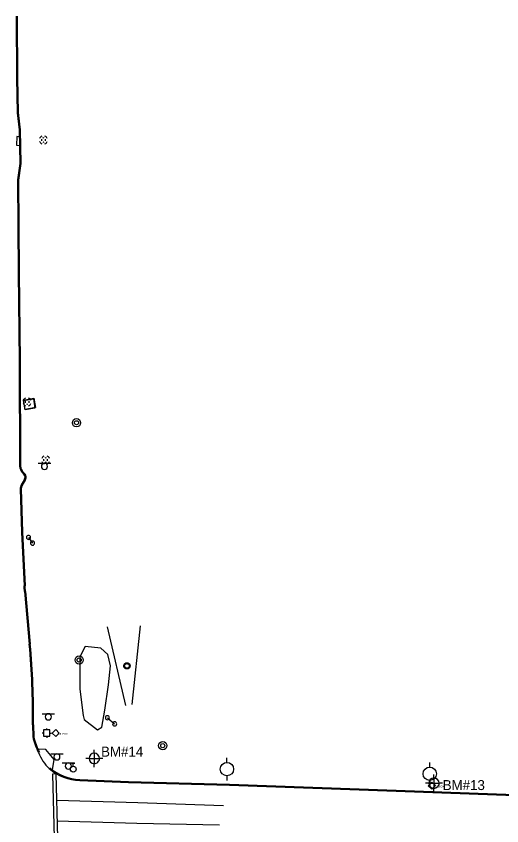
# Model space of a CAD drawing. Extents: x 2145380 to 2157287, y 139568 to 149130.
# Drawn here: x 2145661.6 to 2145954.5, y 143157.2 to 143645.3 of the extents above; entities that cross this region are included whole.
import ezdxf

# ---------------------------------------------------------------- set-up
doc = ezdxf.new("R2010")
doc.units = 0
for name, color, linetype in [('Default', 7, 'Continuous'), ('SURV_Benchmark', 7, 'Continuous'), ('TOPO_Asphalt', 7, 'Continuous'), ('TOPO_Concrete', 7, 'Continuous'), ('TOPO_Curb Back', 7, 'Continuous'), ('TOPO_DRAIN_Inlet Grate', 7, 'Continuous'), ('TOPO_DRAIN_Manhole', 7, 'Continuous'), ('TOPO_Misc', 7, 'Continuous'), ('TOPO_Misc Line', 7, 'Continuous'), ('TOPO_Power Pole', 7, 'Continuous'), ('TOPO_Power Pullbox', 7, 'Continuous'), ('TOPO_San Manhole', 7, 'Continuous'), ('TOPO_Sidewalk', 7, 'Continuous'), ('TOPO_Sign', 7, 'Continuous'), ('TOPO_Traffic Signal', 7, 'Continuous'), ('TOPO_Tree Line', 7, 'Continuous'), ('TOPO_Water Valve', 7, 'Continuous')]:
    doc.layers.add(name, color=color, linetype=linetype)

# ---------------------------------------------------------------- blocks, each defined once
blk = doc.blocks.new('TRFSIG')
at = {"layer": 'TOPO_Traffic Signal'}
for p, q in [((0, 4.7), (0, 7)), ((-4.7, -0.1), (-7.1, -0.1)), ((0, -4.8), (0, -7.2)), ((4.8, -0.1), (7.2, -0.1))]:
    blk.add_line(p, q, dxfattribs=at)
blk.add_lwpolyline([(-4.7, -4.9), (4.8, -4.8), (4.8, 4.7), (-4.7, 4.7), (-4.7, -4.9)], dxfattribs=at)
blk = doc.blocks.new('MHEXST')
at = {"layer": 'TOPO_DRAIN_Manhole'}
for centre, radius, start, end in [((-0.1, 0.3), 12.7, 112.9748, 158.2636), ((-0.1, 0.1), 6.35, 157.9722, 204.161), ((-0.1, 0.1), 6.35, 66.1941, 113.691), ((-0.1, 0.3), 12.7, 22.0744, 68.6991), ((-0.1, 0.1), 6.35, 336.8023, 21.4046), ((-0.1, 0.3), 12.7, 202.6921, 248.1938), ((-0.1, 0.1), 6.35, 248.5791, 293.1995), ((-0.1, 0.3), 12.7, 291.7963, 337.3032)]:
    blk.add_arc(centre, radius, start, end, dxfattribs=at)
blk = doc.blocks.new('POST')
at = {"layer": 'TOPO_Misc'}
for start, end in [(90, 180), (180, 270), (360, 90), (270, 0)]:
    blk.add_arc((0, 0), 3.16, start, end, dxfattribs=at)
blk = doc.blocks.new('POWPOL')
at = {"layer": 'TOPO_Power Pole'}
for p, q in [((0, 10.2), (0, 17.3)), ((0, -10.2), (0, -17.3))]:
    blk.add_line(p, q, dxfattribs=at)
blk.add_circle((0, 0), 10.2, dxfattribs=at)
blk = doc.blocks.new('pulbox')
at = {"layer": 'Default'}
blk.add_lwpolyline([(-5.4, 0), (0, 5.4), (5.4, 0.1), (0, -5.4), (-5.4, 0)], dxfattribs=at)
blk.add_text('PULLBOX', height=2.54, dxfattribs=at).set_placement((2.5, -2.5))
blk = doc.blocks.new('WATVAL')
at = {"layer": 'Default'}
for p, q in [((-2.2, 9), (2.2, 9)), ((0, 4.5), (0, 9))]:
    blk.add_line(p, q, dxfattribs=at)
blk.add_circle((0, 0), 4.5, dxfattribs=at)
blk = doc.blocks.new('EXMHSS')
at = {"layer": 'Default'}
for radius in [6.3, 3.13]:
    blk.add_circle((0, 0), radius, dxfattribs=at)
blk = doc.blocks.new('BM')
at = {"layer": 'SURV_Benchmark'}
for p, q in [((0, 2.49), (0, 4.15)), ((-2.49, 0), (-4.16, 0)), ((4.16, 0), (2.49, 0)), ((0, -4.16), (0, -2.49))]:
    blk.add_line(p, q, dxfattribs=at)
for points in [[(-2.5, 0), (-2.49, 0), (0, 0), (0, -2.49), (0, -2.49)], [(-2.5, 0), (-2.49, 0), (0, 0), (0, -2.49), (0, -2.49)], [(0, 2.49), (0, 2.49), (0, 0), (2.49, 0), (2.49, 0), (2.49, 0)], [(0, 2.49), (0, 2.49), (0, 0), (2.49, 0), (2.49, 0), (2.49, 0), (2.49, 0)]]:
    blk.add_lwpolyline(points, dxfattribs=at)
for start, end in [(90.0638, 180.0068), (0.0638, 90.0068), (0.0638, 90.0068), (180.0638, 270.0068), (180.0638, 270.0068), (269.9472, 359.9927)]:
    blk.add_arc((0, 0), 2.5, start, end, dxfattribs=at)

msp = doc.modelspace()

# ---------------------------------------------------------------- linework, layer by layer
at = {"layer": 'TOPO_Asphalt'}
msp.add_arc((2145702.32, 143212.4), 29.45, 202.0992, 224.8577, dxfattribs=at)
at = {"layer": 'TOPO_Concrete'}
for points in [[(2145666.94, 143407.93), (2145665.94, 143413.57), (2145671.95, 143414.61), (2145672.93, 143408.99), (2145666.94, 143407.93)], [(2145672.21, 143415), (2145673.27, 143409.36), (2145667, 143408.19), (2145665.95, 143413.83), (2145672.21, 143415)]]:
    msp.add_lwpolyline(points, dxfattribs=at)
at = {"layer": 'TOPO_Curb Back'}
for points in [[(2145661.59, 143645.25), (2145661.87, 143607.91), (2145662.17, 143587.08), (2145663.41, 143576.71), (2145663.76, 143556.4), (2145662.37, 143546.52), (2145662.85, 143490.69), (2145663.37, 143437.37), (2145663.52, 143373.95)], [(2145662.19, 143645.26), (2145662.47, 143607.91), (2145662.77, 143587.12), (2145664.01, 143576.75), (2145664.36, 143556.36), (2145662.97, 143546.48), (2145663.45, 143490.69), (2145663.97, 143437.37), (2145664.12, 143374)], [(2145665.19, 143370.08), (2145666.49, 143368.79)], [(2145665.64, 143370.48), (2145666.92, 143369.2)], [(2145666.66, 143366.24), (2145664.46, 143362.29)], [(2145667.17, 143365.93), (2145665, 143362.03)], [(2145663.97, 143360.4), (2145664.86, 143334.15), (2145666.37, 143301.89)], [(2145664.57, 143360.37), (2145665.46, 143334.18), (2145666.97, 143301.93)], [(2145666.57, 143298.36), (2145669.5, 143266.59)], [(2145667.16, 143298.39), (2145670.1, 143266.65)], [(2145671.48, 143218.08), (2145671.57, 143210.77)], [(2145672.08, 143218.08), (2145672.17, 143210.84)], [(2145699.9, 143184.41), (2145729.34, 143183.26), (2145790.28, 143181.57), (2145890.73, 143178.12), (2145962.32, 143175.51), (2146060.83, 143172.36), (2146149.73, 143171.43), (2146238.6, 143172.08)], [(2145699.93, 143185.01), (2145729.36, 143183.86), (2145790.3, 143182.17), (2145890.76, 143178.72), (2145962.34, 143176.11), (2146060.84, 143172.96), (2146149.74, 143172.03), (2146238.59, 143172.68)]]:
    msp.add_lwpolyline(points, dxfattribs=at)
for centre, radius, start, end in [((2145671.8, 143375.23), 8.38, 188.7923, 217.9664), ((2145671.8, 143375.23), 7.78, 189.1207, 217.6899), ((2145664.94, 143367.41), 2.08, 325.9205, 41.769), ((2145664.94, 143367.41), 2.68, 326.5139, 42.1849), ((2145671.9, 143359.34), 8, 158.341, 172.3377), ((2145671.9, 143359.34), 7.4, 158.6374, 171.9547), ((2145593.44, 143296.15), 73.16, 1.7306, 4.5023), ((2145593.44, 143296.15), 73.76, 1.7451, 4.4949), ((2145186.75, 143222.66), 484.75, 359.4576, 5.1992), ((2145186.75, 143222.66), 485.35, 359.4584, 5.1992), ((2145711.06, 143219.9), 40.53, 193.0089, 207.2806), ((2145711.06, 143219.9), 39.93, 193.1014, 207.2806), ((2145701.84, 143216.57), 32.23, 230.7364, 266.5401), ((2145701.84, 143216.57), 31.63, 230.7364, 266.5285)]:
    msp.add_arc(centre, radius, start, end, dxfattribs=at)
at = {"layer": 'TOPO_DRAIN_Inlet Grate'}
msp.add_lwpolyline([(2145663.49, 143572.47), (2145661.98, 143572.68), (2145661.77, 143567.6), (2145663.57, 143567.37)], dxfattribs=at)
at = {"layer": 'TOPO_Misc Line'}
msp.add_lwpolyline([(2145686.63, 143149.98), (2145685.62, 143188.41), (2145683.47, 143188.35), (2145684.48, 143149.92)], close=True, dxfattribs=at)
for points in [[(2145686.03, 143172.69), (2145734.89, 143171.18), (2145786.57, 143169.49)], [(2145686.37, 143160.06), (2145734.37, 143158.7), (2145784.17, 143157.77)]]:
    msp.add_lwpolyline(points, dxfattribs=at)
at = {"layer": 'TOPO_Power Pole'}
for points in [[(2145726.52, 143253.58), (2145726.53, 143253.71), (2145726.54, 143253.84), (2145726.57, 143253.96), (2145726.6, 143254.09), (2145726.64, 143254.22), (2145726.69, 143254.34), (2145726.75, 143254.46), (2145726.82, 143254.58), (2145726.9, 143254.69), (2145726.98, 143254.79), (2145727.06, 143254.89), (2145727.16, 143254.98), (2145727.26, 143255.06), (2145727.37, 143255.14), (2145727.49, 143255.21), (2145727.61, 143255.27), (2145727.72, 143255.32), (2145727.85, 143255.36), (2145727.98, 143255.4), (2145728.11, 143255.42), (2145728.24, 143255.44), (2145728.38, 143255.44), (2145728.5, 143255.44), (2145728.63, 143255.43), (2145728.76, 143255.41), (2145728.89, 143255.38), (2145729.02, 143255.34), (2145729.14, 143255.29), (2145729.26, 143255.24), (2145729.38, 143255.17), (2145729.49, 143255.1), (2145729.59, 143255.02), (2145729.69, 143254.93), (2145729.78, 143254.84), (2145729.87, 143254.73), (2145729.94, 143254.62), (2145730.02, 143254.51), (2145730.08, 143254.4), (2145730.13, 143254.27), (2145730.18, 143254.15), (2145730.21, 143254.02), (2145730.24, 143253.89), (2145730.26, 143253.76), (2145730.27, 143253.63), (2145730.27, 143253.5), (2145730.26, 143253.37), (2145730.23, 143253.24), (2145730.21, 143253.11), (2145730.17, 143252.98), (2145730.13, 143252.86), (2145730.07, 143252.74), (2145730.01, 143252.62), (2145729.93, 143252.51), (2145729.85, 143252.4), (2145729.77, 143252.3), (2145729.67, 143252.21), (2145729.58, 143252.13), (2145729.47, 143252.04), (2145729.36, 143251.97), (2145729.24, 143251.91), (2145729.12, 143251.85), (2145729, 143251.8), (2145728.87, 143251.77), (2145728.74, 143251.74), (2145728.61, 143251.72), (2145728.48, 143251.71), (2145728.35, 143251.71), (2145728.22, 143251.72), (2145728.09, 143251.73), (2145727.96, 143251.76), (2145727.83, 143251.79), (2145727.71, 143251.84), (2145727.58, 143251.89), (2145727.47, 143251.96), (2145727.36, 143252.02), (2145727.25, 143252.1), (2145727.14, 143252.19), (2145727.05, 143252.28), (2145726.96, 143252.38), (2145726.88, 143252.49), (2145726.81, 143252.59), (2145726.74, 143252.7), (2145726.68, 143252.83), (2145726.63, 143252.95), (2145726.59, 143253.08), (2145726.57, 143253.2), (2145726.54, 143253.34), (2145726.53, 143253.47), (2145726.52, 143253.58)], [(2145726.99, 143253.58), (2145727, 143253.69), (2145727.01, 143253.8), (2145727.03, 143253.91), (2145727.07, 143254.02), (2145727.11, 143254.13), (2145727.16, 143254.24), (2145727.22, 143254.33), (2145727.28, 143254.43), (2145727.36, 143254.51), (2145727.44, 143254.59), (2145727.53, 143254.68), (2145727.62, 143254.74), (2145727.72, 143254.8), (2145727.82, 143254.85), (2145727.92, 143254.89), (2145728.03, 143254.93), (2145728.15, 143254.95), (2145728.26, 143254.98), (2145728.38, 143254.98), (2145728.48, 143254.98), (2145728.59, 143254.97), (2145728.71, 143254.94), (2145728.82, 143254.91), (2145728.93, 143254.87), (2145729.03, 143254.83), (2145729.13, 143254.77), (2145729.23, 143254.7), (2145729.32, 143254.63), (2145729.4, 143254.56), (2145729.48, 143254.47), (2145729.55, 143254.37), (2145729.61, 143254.28), (2145729.66, 143254.18), (2145729.71, 143254.07), (2145729.74, 143253.96), (2145729.78, 143253.85), (2145729.79, 143253.74), (2145729.8, 143253.63), (2145729.8, 143253.52), (2145729.79, 143253.41), (2145729.77, 143253.29), (2145729.74, 143253.18), (2145729.7, 143253.07), (2145729.66, 143252.97), (2145729.61, 143252.87), (2145729.54, 143252.77), (2145729.48, 143252.68), (2145729.39, 143252.59), (2145729.31, 143252.51), (2145729.22, 143252.44), (2145729.12, 143252.38), (2145729.03, 143252.32), (2145728.92, 143252.27), (2145728.82, 143252.24), (2145728.7, 143252.21), (2145728.59, 143252.19), (2145728.47, 143252.18), (2145728.37, 143252.18), (2145728.25, 143252.19), (2145728.14, 143252.2), (2145728.02, 143252.22), (2145727.91, 143252.26), (2145727.81, 143252.3), (2145727.71, 143252.35), (2145727.61, 143252.42), (2145727.52, 143252.49), (2145727.43, 143252.56), (2145727.35, 143252.64), (2145727.28, 143252.73), (2145727.21, 143252.83), (2145727.16, 143252.92), (2145727.11, 143253.03), (2145727.06, 143253.14), (2145727.03, 143253.25), (2145727.01, 143253.36), (2145727, 143253.47), (2145726.99, 143253.58)]]:
    msp.add_lwpolyline(points, dxfattribs=at)
at = {"layer": 'TOPO_Sidewalk'}
msp.add_lwpolyline([(2145683.41, 143190.87), (2145684.54, 143197.07), (2145679.39, 143203.15), (2145674.68, 143203.43), (2145674.68, 143203.47)], dxfattribs=at)
at = {"layer": 'TOPO_Sign'}
for points in [[(2145674.9, 143375.73), (2145682.39, 143375.74)], [(2145678.65, 143375.73), (2145678.65, 143375.73)], [(2145676.78, 143373.86), (2145676.78, 143373.86)], [(2145678.65, 143372), (2145678.65, 143372)], [(2145680.51, 143373.86), (2145680.51, 143373.86)], [(2145669.01, 143331.02), (2145671.45, 143327.59)], [(2145716.55, 143277.07), (2145727.52, 143229.77)], [(2145731.52, 143230.36), (2145736.66, 143277.75)], [(2145677.2, 143224.72), (2145684.7, 143224.73)], [(2145680.95, 143224.72), (2145680.95, 143224.72)], [(2145679.08, 143222.85), (2145679.08, 143222.85)], [(2145680.95, 143220.99), (2145680.95, 143220.99)], [(2145682.82, 143222.85), (2145682.82, 143222.85)], [(2145716.6, 143222.3), (2145720.98, 143218.61)], [(2145682.39, 143200.58), (2145689.88, 143200.59)], [(2145686.14, 143200.58), (2145686.14, 143200.58)], [(2145684.27, 143198.72), (2145684.27, 143198.72)], [(2145686.14, 143196.85), (2145686.14, 143196.85)], [(2145688, 143198.72), (2145688, 143198.72)], [(2145689.25, 143195.04), (2145696.74, 143195.04)], [(2145693, 143195.04), (2145693, 143195.04)], [(2145691.13, 143193.17), (2145691.13, 143193.17)], [(2145693, 143191.3), (2145693, 143191.3)], [(2145694.87, 143193.17), (2145694.87, 143193.17)]]:
    msp.add_lwpolyline(points, dxfattribs=at)
for centre, start, end in [((2145678.65, 143373.86), 90, 180), ((2145678.65, 143373.86), 360, 90), ((2145678.65, 143373.86), 180, 270), ((2145678.65, 143373.86), 270, 0), ((2145680.95, 143222.85), 90, 180), ((2145680.95, 143222.85), 360, 90), ((2145680.95, 143222.85), 180, 270), ((2145680.95, 143222.85), 270, 0), ((2145686.14, 143198.72), 90, 180), ((2145686.14, 143198.72), 360, 90), ((2145686.14, 143198.72), 180, 270), ((2145686.14, 143198.72), 270, 0), ((2145693, 143193.17), 90, 180), ((2145693, 143193.17), 360, 90), ((2145693, 143193.17), 180, 270), ((2145693, 143193.17), 270, 0)]:
    msp.add_arc(centre, 1.87, start, end, dxfattribs=at)
at = {"layer": 'TOPO_Tree Line'}
msp.add_lwpolyline([(2145702.64, 143221.25), (2145710.6, 143215.05), (2145713.22, 143216.64), (2145715, 143226.8), (2145717.34, 143242.18), (2145718.48, 143253.61), (2145716.85, 143260.46), (2145712.64, 143264.32), (2145703.2, 143265.24), (2145700.04, 143259.1), (2145700.07, 143251.3), (2145699.99, 143239.51), (2145702.04, 143223.59), (2145702.64, 143221.25)], dxfattribs=at)

# ---------------------------------------------------------------- block references
at = {"layer": 'SURV_Benchmark', "xscale": 1.25, "yscale": 1.25}
for p in [(2145708.71, 143197.81), (2145913.57, 143182.85)]:
    msp.add_blockref('BM', p, dxfattribs=at)
at = {"layer": 'TOPO_DRAIN_Manhole', "xscale": 0.19685000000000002, "yscale": 0.19685000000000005}
for p in [(2145678.05, 143570.56), (2145668.19, 143412.66), (2145679.34, 143377.67)]:
    msp.add_blockref('MHEXST', p, dxfattribs=at)
at = {"layer": 'TOPO_Misc', "xscale": 0.39370000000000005, "yscale": 0.3937000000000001}
for p in [(2145669.01, 143331.02), (2145671.45, 143327.59), (2145716.6, 143222.3), (2145720.98, 143218.61)]:
    msp.add_blockref('POST', p, dxfattribs=at)
at = {"layer": 'TOPO_Power Pole', "xscale": 0.39370000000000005, "yscale": 0.3937000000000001}
for p in [(2145788.71, 143191.34), (2145911, 143188.52)]:
    msp.add_blockref('POWPOL', p, dxfattribs=at)
at = {"layer": 'TOPO_Power Pullbox', "xscale": 0.39370000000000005, "yscale": 0.3937000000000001}
for p in [(2145685.44, 143213.07), (2145912.27, 143181.35)]:
    msp.add_blockref('pulbox', p, dxfattribs=at)
at = {"layer": 'TOPO_San Manhole', "xscale": 0.39370000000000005, "yscale": 0.3937000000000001}
for p in [(2145697.99, 143400.14), (2145699.58, 143257.11), (2145749.99, 143205.49)]:
    msp.add_blockref('EXMHSS', p, dxfattribs=at)
at = {"layer": 'TOPO_Traffic Signal', "xscale": 0.39370000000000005, "yscale": 0.3937000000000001}
msp.add_blockref('TRFSIG', (2145680.01, 143213.08), dxfattribs=at)
at = {"layer": 'TOPO_Water Valve', "xscale": 0.39370000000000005, "yscale": 0.3937000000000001}
msp.add_blockref('WATVAL', (2145696.02, 143191.32), dxfattribs=at)

# ---------------------------------------------------------------- texts
at = {"layer": 'SURV_Benchmark'}
msp.add_text('BM#14', height=6, rotation=360, dxfattribs=at).set_placement((2145712.8, 143198.87))
msp.add_text('BM#13', height=6, dxfattribs=at).set_placement((2145918.85, 143178.72))

doc.saveas('drawing.dxf')
